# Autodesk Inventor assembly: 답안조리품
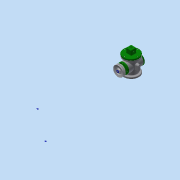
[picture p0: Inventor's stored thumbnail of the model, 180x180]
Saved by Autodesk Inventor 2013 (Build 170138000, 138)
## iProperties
Created: 2018-02
Part Number: 답안조리품
Document SubType Name: Assembly
Designer: Administrator
Author: Administrator
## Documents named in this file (18)
- C:\Users\Administrator\Desktop\480207v1019\답안조리품.iam
- C:\Users\Administrator\Desktop\480207v1019\E-링.ipt
- C:\Users\Administrator\Desktop\480207v1019\V-벨트풀리.ipt
- C:\Users\Administrator\Desktop\480207v1019\덮개.ipt
- C:\Users\Administrator\Desktop\480207v1019\뒤커버.ipt
- C:\Users\Administrator\Desktop\480207v1019\링크.ipt
- C:\Users\Administrator\Desktop\480207v1019\베어링 17 x 40 x 12.ipt
- C:\Users\Administrator\Desktop\480207v1019\본체1.ipt
- C:\Users\Administrator\Desktop\480207v1019\볼트 M4 x 8.ipt
- C:\Users\Administrator\Desktop\480207v1019\볼트 M4 x 10.ipt
- C:\Users\Administrator\Desktop\480207v1019\슬라이더.ipt
- C:\Users\Administrator\Desktop\480207v1019\앞커버.ipt
- C:\Users\Administrator\Desktop\480207v1019\오일 실 17 30 8.ipt
- C:\Users\Administrator\Desktop\480207v1019\와셔 4x16.ipt
- C:\Users\Administrator\Desktop\480207v1019\클레비스 핀 6 x 22.ipt
- 클레비스 핀 6 x 22.ipt
- C:\Users\Administrator\Desktop\480207v1019\키 4 x 4 x 12.ipt
- C:\Users\Administrator\Desktop\480207v1019\편심축.ipt
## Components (3 placed, 2 different names)
1. E-링:1
2. E-링:2
3. V-벨트풀리:2
